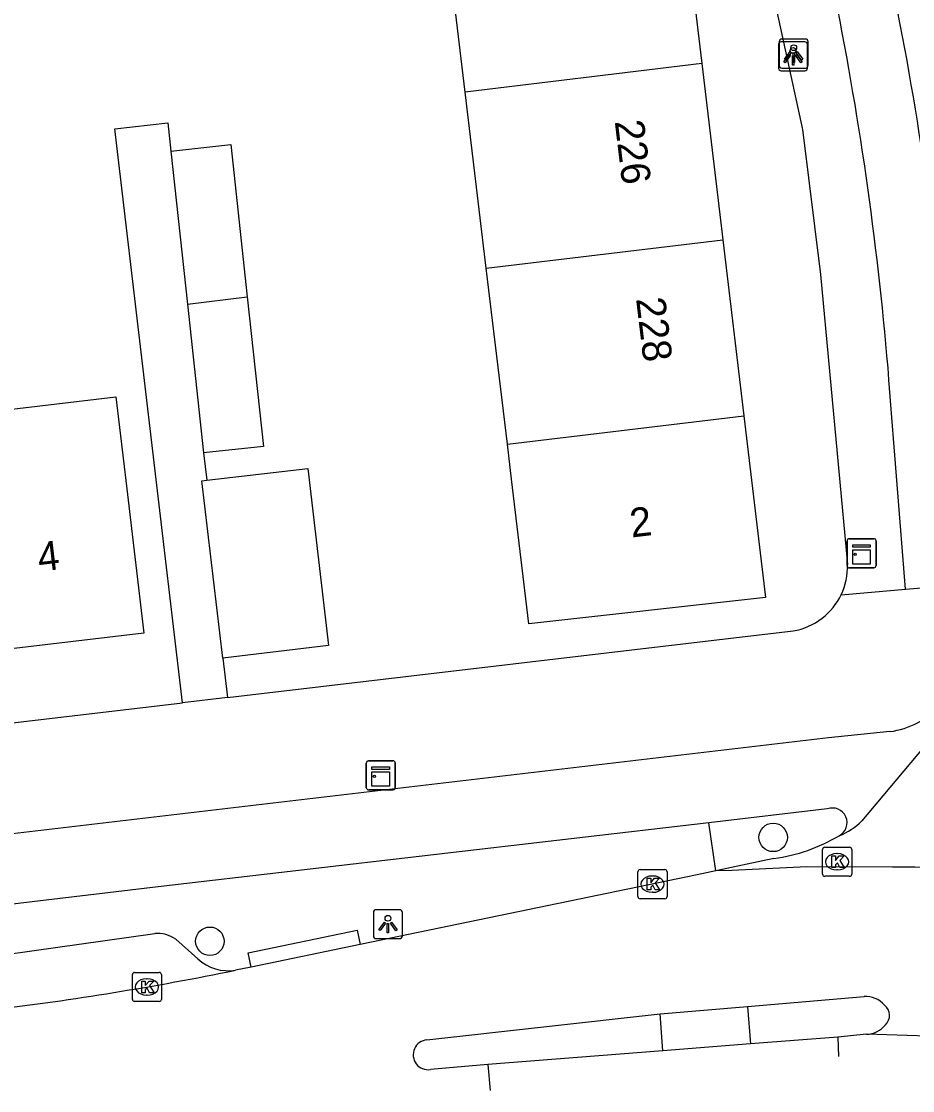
# Model space of a CAD drawing. Extents: x 159888 to 160757, y 384031 to 384746.
# Drawn here: x 160535.91 to 160566.56, y 384159.71 to 384196.47 of the extents above; entities that cross this region are included whole.
import ezdxf

# ---------------------------------------------------------------- set-up
doc = ezdxf.new("R2010")
doc.units = 0
for name, color, linetype in [('IMGEO_Boom', 7, 'Continuous'), ('IMGEO_Fietspad_open', 7, 'Continuous'), ('IMGEO_Kast', 7, 'Continuous'), ('IMGEO_Kolk', 7, 'Continuous'), ('IMGEO_Lichtpunt', 7, 'Continuous'), ('IMGEO_Pand', 7, 'Continuous'), ('IMGEO_Pand_nummerreeks', 7, 'Continuous'), ('IMGEO_Parkeervlak_open', 7, 'Continuous'), ('IMGEO_Rijbaan_lokaal_gesloten', 7, 'Continuous'), ('IMGEO_Rijbaan_lokaal_open', 7, 'Continuous'), ('IMGEO_Verkeerseiland_open', 7, 'Continuous'), ('IMGEO_Voetpad_open', 7, 'Continuous')]:
    doc.layers.add(name, color=color, linetype=linetype)

msp = doc.modelspace()

# ---------------------------------------------------------------- linework, layer by layer
at = {"layer": 'IMGEO_Boom'}
for centre in [(160561.769, 384168.415), (160542.395, 384164.844)]:
    msp.add_circle(centre, 0.489, dxfattribs=at)
at = {"layer": 'IMGEO_Fietspad_open'}
for points in [[(160565.78, 384172.052), (160563.669, 384171.834), (160511.035, 384165.652)], [(160563.629, 384169.394), (160559.552, 384168.92)], [(160559.552, 384168.92), (160540.617, 384166.718), (160510.075, 384163.087)]]:
    msp.add_lwpolyline(points, dxfattribs=at)
for centre, radius, start, end in [((160565.38, 384174.941), 2.917, 277.8919, 317.2968), ((160563.806, 384168.92), 0.506, 297.618, 110.4338)]:
    msp.add_arc(centre, radius, start, end, dxfattribs=at)
at = {"layer": 'IMGEO_Kast'}
for p, q in [((160564.309, 384177.76), (160564.309, 384178.601)), ((160564.309, 384178.601), (160564.309, 384177.76)), ((160564.384, 384178.685), (160565.225, 384178.685)), ((160565.225, 384178.685), (160564.384, 384178.685)), ((160565.309, 384178.61), (160565.309, 384177.769)), ((160565.309, 384177.769), (160565.309, 384178.61)), ((160565.234, 384177.685), (160564.393, 384177.685)), ((160564.393, 384177.685), (160565.234, 384177.685)), ((160547.848, 384171.049), (160548.689, 384171.049)), ((160548.689, 384171.049), (160547.848, 384171.049)), ((160547.773, 384170.124), (160547.773, 384170.965)), ((160547.773, 384170.965), (160547.773, 384170.124)), ((160548.773, 384170.974), (160548.773, 384170.133)), ((160548.773, 384170.133), (160548.773, 384170.974)), ((160548.698, 384170.049), (160547.857, 384170.049)), ((160547.857, 384170.049), (160548.698, 384170.049))]:
    msp.add_line(p, q, dxfattribs=at)
for points in [[(160564.504, 384178.475), (160565.104, 384178.475), (160565.104, 384178.39), (160564.504, 384178.39), (160564.504, 384178.475)], [(160564.504, 384178.3), (160565.104, 384178.3), (160565.104, 384177.811), (160564.504, 384177.811), (160564.504, 384178.3)], [(160547.968, 384170.839), (160548.568, 384170.839), (160548.568, 384170.754), (160547.968, 384170.754), (160547.968, 384170.839)], [(160547.968, 384170.664), (160548.568, 384170.664), (160548.568, 384170.175), (160547.968, 384170.175), (160547.968, 384170.664)]]:
    msp.add_lwpolyline(points, dxfattribs=at)
for centre in [(160564.588, 384178.149), (160548.052, 384170.513)]:
    msp.add_circle(centre, 0.0377, dxfattribs=at)
for centre, start, end in [((160564.387, 384178.607), 92.4484, 184.2845), ((160564.387, 384178.607), 92.4484, 184.2845), ((160565.231, 384178.607), 2.4484, 94.2845), ((160565.231, 384178.607), 2.4484, 94.2845), ((160564.387, 384177.763), 182.4484, 274.2845), ((160564.387, 384177.763), 182.4484, 274.2845), ((160565.231, 384177.763), 272.4484, 4.2845), ((160565.231, 384177.763), 272.4484, 4.2845), ((160547.851, 384170.971), 92.4484, 184.2845), ((160547.851, 384170.971), 92.4484, 184.2845), ((160548.695, 384170.971), 2.4484, 94.2845), ((160548.695, 384170.971), 2.4484, 94.2845), ((160547.851, 384170.127), 182.4484, 274.2845), ((160547.851, 384170.127), 182.4484, 274.2845), ((160548.695, 384170.127), 272.4484, 4.2845), ((160548.695, 384170.127), 272.4484, 4.2845)]:
    msp.add_arc(centre, 0.0779, start, end, dxfattribs=at)
at = {"layer": 'IMGEO_Kolk'}
for p, q in [((160563.543, 384168.077), (160564.395, 384168.077)), ((160563.468, 384167.151), (160563.468, 384168.003)), ((160563.956, 384167.857), (160563.981, 384167.857)), ((160564.469, 384168.003), (160564.469, 384167.151)), ((160557.117, 384166.382), (160557.117, 384167.234)), ((160557.192, 384167.308), (160558.044, 384167.308)), ((160557.605, 384167.088), (160557.63, 384167.088)), ((160558.118, 384167.234), (160558.118, 384166.382)), ((160564.395, 384167.077), (160563.543, 384167.077)), ((160563.979, 384167.297), (160563.954, 384167.297)), ((160558.044, 384166.308), (160557.192, 384166.308)), ((160557.628, 384166.528), (160557.603, 384166.528)), ((160539.729, 384162.847), (160539.729, 384163.699)), ((160539.804, 384163.773), (160540.656, 384163.773)), ((160540.73, 384163.699), (160540.73, 384162.847)), ((160540.217, 384163.553), (160540.242, 384163.553)), ((160540.24, 384162.993), (160540.215, 384162.993)), ((160540.656, 384162.773), (160539.804, 384162.773))]:
    msp.add_line(p, q, dxfattribs=at)
for points in [[(160563.543, 384168.077), (160564.395, 384168.077)], [(160563.468, 384167.151), (160563.468, 384168.003)], [(160563.789, 384167.777), (160563.912, 384167.777), (160563.912, 384167.626), (160564.042, 384167.777), (160564.206, 384167.777), (160564.06, 384167.626), (160564.213, 384167.377), (160564.061, 384167.377), (160563.976, 384167.541), (160563.912, 384167.474), (160563.912, 384167.377), (160563.789, 384167.377), (160563.789, 384167.777)], [(160564.469, 384168.003), (160564.469, 384167.151)], [(160557.117, 384166.382), (160557.117, 384167.234)], [(160557.192, 384167.308), (160558.044, 384167.308)], [(160557.438, 384167.008), (160557.561, 384167.008), (160557.561, 384166.857), (160557.691, 384167.008), (160557.855, 384167.008), (160557.709, 384166.857), (160557.862, 384166.608), (160557.71, 384166.608), (160557.625, 384166.772), (160557.561, 384166.705), (160557.561, 384166.608), (160557.438, 384166.608), (160557.438, 384167.008)], [(160558.118, 384167.234), (160558.118, 384166.382)], [(160564.395, 384167.077), (160563.543, 384167.077)], [(160558.044, 384166.308), (160557.192, 384166.308)], [(160539.729, 384162.847), (160539.729, 384163.699)], [(160539.804, 384163.773), (160540.656, 384163.773)], [(160540.73, 384163.699), (160540.73, 384162.847)], [(160540.05, 384163.473), (160540.173, 384163.473), (160540.173, 384163.322), (160540.303, 384163.473), (160540.467, 384163.473), (160540.321, 384163.322), (160540.474, 384163.073), (160540.322, 384163.073), (160540.237, 384163.237), (160540.173, 384163.17), (160540.173, 384163.073), (160540.05, 384163.073), (160540.05, 384163.473)], [(160540.656, 384162.773), (160539.804, 384162.773)]]:
    msp.add_lwpolyline(points, dxfattribs=at)
for centre, start, end in [((160563.545, 384168.001), 91.552, 178.448), ((160563.545, 384168.001), 91.552, 178.448), ((160564.393, 384168.001), 1.552, 88.448), ((160564.393, 384168.001), 1.552, 88.448), ((160557.194, 384167.232), 91.552, 178.448), ((160557.194, 384167.232), 91.552, 178.448), ((160558.042, 384167.232), 1.552, 88.448), ((160558.042, 384167.232), 1.552, 88.448), ((160563.545, 384167.153), 181.552, 268.448), ((160563.545, 384167.153), 181.552, 268.448), ((160564.393, 384167.153), 271.552, 358.448), ((160564.393, 384167.153), 271.552, 358.448), ((160557.194, 384166.384), 181.552, 268.448), ((160557.194, 384166.384), 181.552, 268.448), ((160558.042, 384166.384), 271.552, 358.448), ((160558.042, 384166.384), 271.552, 358.448), ((160539.806, 384163.697), 91.552, 178.448), ((160539.806, 384163.697), 91.552, 178.448), ((160540.654, 384163.697), 1.552, 88.448), ((160540.654, 384163.697), 1.552, 88.448), ((160539.806, 384162.849), 181.552, 268.448), ((160539.806, 384162.849), 181.552, 268.448), ((160540.654, 384162.849), 271.552, 358.448), ((160540.654, 384162.849), 271.552, 358.448)]:
    msp.add_arc(centre, 0.0765, start, end, dxfattribs=at)
for centre, major_axis, ratio, start_param, end_param in [((160563.955, 384167.577), (-0.387, 0.002), 0.722429, 4.712389, 7.853982), ((160563.98, 384167.577), (-0.39, 0.002), 0.717154, 1.570796, 4.712389), ((160557.604, 384166.808), (-0.387, 0.002), 0.722429, 4.712389, 7.853982), ((160557.629, 384166.808), (-0.39, 0.002), 0.717154, 1.570796, 4.712389), ((160540.216, 384163.273), (-0.387, 0.002), 0.722429, 4.712389, 7.853982), ((160540.241, 384163.273), (-0.39, 0.002), 0.717154, 1.570796, 4.712389)]:
    msp.add_ellipse(centre, major_axis=major_axis, ratio=ratio, start_param=start_param, end_param=end_param, dxfattribs=at)
at = {"layer": 'IMGEO_Lichtpunt'}
for p, q in [((160561.952, 384195.676), (160561.952, 384194.869)), ((160561.952, 384195.676), (160561.952, 384194.869)), ((160561.975, 384195.77), (160561.975, 384194.963)), ((160561.975, 384195.77), (160561.975, 384194.963)), ((160562.854, 384195.771), (160562.046, 384195.771)), ((160562.854, 384195.771), (160562.046, 384195.771)), ((160562.877, 384195.865), (160562.069, 384195.865)), ((160562.877, 384195.865), (160562.069, 384195.865)), ((160562.948, 384194.869), (160562.948, 384195.676)), ((160562.948, 384194.869), (160562.948, 384195.676)), ((160562.971, 384194.963), (160562.971, 384195.77)), ((160562.971, 384194.963), (160562.971, 384195.77)), ((160562.046, 384194.775), (160562.854, 384194.775)), ((160562.046, 384194.775), (160562.854, 384194.775)), ((160562.069, 384194.869), (160562.877, 384194.869)), ((160562.069, 384194.869), (160562.877, 384194.869)), ((160548.923, 384165.93), (160548.115, 384165.93)), ((160548.923, 384165.93), (160548.115, 384165.93)), ((160548.021, 384165.835), (160548.021, 384165.028)), ((160548.021, 384165.835), (160548.021, 384165.028)), ((160549.017, 384165.028), (160549.017, 384165.835)), ((160549.017, 384165.028), (160549.017, 384165.835)), ((160548.115, 384164.934), (160548.923, 384164.934)), ((160548.115, 384164.934), (160548.923, 384164.934))]:
    msp.add_line(p, q, dxfattribs=at)
for points in [[(160562.326, 384195.34), (160562.365, 384195.312), (160562.177, 384195.05), (160562.139, 384195.077), (160562.326, 384195.34)], [(160562.349, 384195.434), (160562.388, 384195.406), (160562.2, 384195.144), (160562.162, 384195.171), (160562.349, 384195.434)], [(160562.428, 384195.292), (160562.475, 384195.292), (160562.475, 384194.97), (160562.428, 384194.97), (160562.428, 384195.292)], [(160562.451, 384195.386), (160562.498, 384195.386), (160562.498, 384195.064), (160562.451, 384195.064), (160562.451, 384195.386)], [(160562.538, 384195.312), (160562.576, 384195.339), (160562.763, 384195.077), (160562.724, 384195.049), (160562.538, 384195.312)], [(160562.561, 384195.406), (160562.599, 384195.433), (160562.786, 384195.171), (160562.747, 384195.143), (160562.561, 384195.406)], [(160548.395, 384165.499), (160548.434, 384165.471), (160548.246, 384165.209), (160548.208, 384165.236), (160548.395, 384165.499)], [(160548.607, 384165.471), (160548.645, 384165.498), (160548.832, 384165.236), (160548.793, 384165.208), (160548.607, 384165.471)], [(160548.497, 384165.451), (160548.544, 384165.451), (160548.544, 384165.129), (160548.497, 384165.129), (160548.497, 384165.451)]]:
    msp.add_lwpolyline(points, dxfattribs=at)
for centre in [(160562.474, 384195.568), (160562.451, 384195.474), (160548.52, 384165.633)]:
    msp.add_circle(centre, 0.0994, dxfattribs=at)
for centre, start, end in [((160562.046, 384195.676), 90, 180), ((160562.046, 384195.676), 90, 180), ((160562.069, 384195.77), 90, 180), ((160562.069, 384195.77), 90, 180), ((160562.854, 384195.676), 0, 90), ((160562.854, 384195.676), 0, 90), ((160562.877, 384195.77), 0, 90), ((160562.877, 384195.77), 0, 90), ((160562.069, 384194.963), 180, 270), ((160562.069, 384194.963), 180, 270), ((160562.877, 384194.963), 270, 0), ((160562.877, 384194.963), 270, 360), ((160562.046, 384194.869), 180, 270), ((160562.046, 384194.869), 180, 270), ((160562.854, 384194.869), 270, 0), ((160562.854, 384194.869), 270, 360), ((160548.115, 384165.835), 90, 180), ((160548.115, 384165.835), 90, 180), ((160548.923, 384165.835), 0, 90), ((160548.923, 384165.835), 0, 90), ((160548.115, 384165.028), 180, 270), ((160548.115, 384165.028), 180, 270), ((160548.923, 384165.028), 270, 0), ((160548.923, 384165.028), 270, 360)]:
    msp.add_arc(centre, 0.0946, start, end, dxfattribs=at)
at = {"layer": 'IMGEO_Pand'}
for points in [[(160554.014, 384204.247), (160555.198, 384200.789), (160558.586, 384201.159), (160559.314, 384195.02)], [(160551.177, 384194.043), (160550.476, 384199.882), (160547.111, 384199.478), (160546.382, 384201.607)], [(160559.314, 384195.02), (160551.177, 384194.043)], [(160559.314, 384195.02), (160559.93, 384189.828), (160560.033, 384188.963)], [(160551.903, 384187.987), (160551.177, 384194.043)], [(160541.053, 384192.014), (160543.114, 384192.237), (160543.681, 384187)], [(160541.053, 384192.014), (160541.623, 384186.753)], [(160551.903, 384187.987), (160560.033, 384188.963)], [(160560.033, 384188.963), (160560.758, 384182.906)], [(160552.63, 384181.93), (160551.903, 384187.987)], [(160541.623, 384186.753), (160543.681, 384187)], [(160543.681, 384187), (160544.238, 384181.858), (160542.177, 384181.635)], [(160541.623, 384186.753), (160542.177, 384181.635)], [(160533.056, 384182.845), (160539.164, 384183.563), (160539.535, 384180.402), (160540.119, 384175.436), (160534.002, 384174.717)], [(160560.758, 384182.906), (160561.505, 384176.663), (160553.37, 384175.763), (160552.774, 384180.728), (160552.63, 384181.93)], [(160552.63, 384181.93), (160560.758, 384182.906)], [(160542.287, 384180.695), (160545.764, 384181.103), (160546.48, 384175.01), (160542.837, 384174.582)], [(160542.837, 384174.582), (160542.121, 384180.675), (160542.287, 384180.695)]]:
    msp.add_lwpolyline(points, dxfattribs=at)
at = {"layer": 'IMGEO_Parkeervlak_open'}
for points in [[(160517.411, 384161.098), (160517.955, 384161.94), (160518.409, 384162.327), (160534.554, 384164.276), (160540.497, 384165.109)], [(160541.221, 384164.913), (160541.976, 384164.237)]]:
    msp.add_lwpolyline(points, dxfattribs=at)
for centre, radius, start, end in [((160540.59, 384164.018), 1.095, 54.8252, 94.8789), ((160543.04, 384165.422), 1.592, 228.0944, 278.6846)]:
    msp.add_arc(centre, radius, start, end, dxfattribs=at)
at = {"layer": 'IMGEO_Rijbaan_lokaal_gesloten'}
for points in [[(160565.877, 384167.394), (160562.923, 384167.402), (160560.349, 384167.273), (160559.791, 384167.26)], [(160559.791, 384167.26), (160559.154, 384167.124), (160547.567, 384164.732)], [(160547.567, 384164.732), (160543.818, 384163.958)], [(160543.818, 384163.958), (160543.28, 384163.848)], [(160560.888, 384162.604), (160564.893, 384162.947)], [(160557.886, 384162.345), (160560.888, 384162.604)], [(160549.862, 384161.451), (160557.886, 384162.345)], [(160563.995, 384161.549), (160560.993, 384161.313)], [(160564.979, 384161.647), (160563.995, 384161.549)], [(160563.995, 384161.549), (160564.02, 384160.883)], [(160577.411, 384160.087), (160571.411, 384161.3), (160568.473, 384161.54), (160564.979, 384161.647)], [(160557.97, 384161.076), (160551.957, 384160.605)], [(160560.993, 384161.313), (160557.97, 384161.076)], [(160551.957, 384160.605), (160549.981, 384160.435)], [(160551.957, 384160.605), (160552.039, 384159.709)]]:
    msp.add_lwpolyline(points, dxfattribs=at)
for centre, radius, start, end in [((160565.991, 384139.099), 28.296, 81.973, 90.2304), ((160522.284, 384266.701), 104.974, 276.89507, 281.53777), ((160564.949, 384162.098), 0.851, 40.1737, 93.7822), ((160565.325, 384162.293), 0.447, 313.2871, 52.2778), ((160564.946, 384162.538), 0.892, 272.0994, 320.256), ((160549.9, 384160.941), 0.512, 94.3063, 279.0545)]:
    msp.add_arc(centre, radius, start, end, dxfattribs=at)
at = {"layer": 'IMGEO_Rijbaan_lokaal_open'}
for points in [[(160567.224, 384171.854), (160564.82, 384168.981)], [(160561.795, 384167.687), (160559.791, 384167.26)]]:
    msp.add_lwpolyline(points, dxfattribs=at)
for centre, radius, start, end in [((160468.958, 384177.359), 99.02, 3.97147, 11.80346), ((160563.203, 384170.606), 2.292, 291.4057, 314.8483), ((160560.936, 384173.746), 6.119, 278.0673, 300.4786)]:
    msp.add_arc(centre, radius, start, end, dxfattribs=at)
at = {"layer": 'IMGEO_Verkeerseiland_open'}
msp.add_lwpolyline([(160559.791, 384167.26), (160559.552, 384168.92)], dxfattribs=at)
at = {"layer": 'IMGEO_Voetpad_open'}
for points in [[(160516.041, 384278.668), (160533.512, 384250), (160556.908, 384211.788), (160559.072, 384207.22), (160560.667, 384202.459), (160562.778, 384192.752), (160563.394, 384187.766), (160564.326, 384177.793)], [(160541.448, 384173.043), (160539.127, 384192.783), (160540.948, 384192.981), (160541.053, 384192.014)], [(160566.321, 384176.95), (160565.752, 384184.144)], [(160542.177, 384181.635), (160542.287, 384180.695)], [(160564.104, 384176.756), (160566.321, 384176.95)], [(160566.321, 384176.95), (160567.836, 384177.075)], [(160542.997, 384173.226), (160562.457, 384175.514)], [(160542.837, 384174.582), (160542.997, 384173.226)], [(160542.997, 384173.226), (160541.448, 384173.043)], [(160510.194, 384169.368), (160541.448, 384173.043)], [(160543.818, 384163.958), (160543.717, 384164.447), (160547.466, 384165.221), (160547.567, 384164.732)], [(160560.888, 384162.604), (160560.993, 384161.313)], [(160557.97, 384161.076), (160557.886, 384162.345)]]:
    msp.add_lwpolyline(points, dxfattribs=at)
for centre, radius, start, end in [((160453.796, 384175.144), 112.317, 4.59609, 11.37491), ((160562.08, 384177.732), 2.247, 334.2688, 1.5643), ((160562.075, 384177.73), 2.251, 307.8454, 334.3494), ((160562.076, 384177.738), 2.256, 279.7281, 307.7171)]:
    msp.add_arc(centre, radius, start, end, dxfattribs=at)

# ---------------------------------------------------------------- texts
at = {"layer": 'IMGEO_Pand_nummerreeks'}
for s, rotation, p in [('226', 276.8466, (160556.318, 384193.036)), ('228', 276.8466, (160557.05, 384186.937)), ('2', 6.8354, (160556.898, 384178.724)), ('4', 6.7064, (160536.527, 384177.551))]:
    msp.add_text(s, height=1, rotation=rotation, dxfattribs=at).set_placement(p)

doc.saveas('drawing.dxf')
